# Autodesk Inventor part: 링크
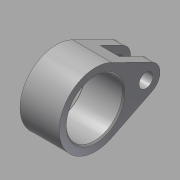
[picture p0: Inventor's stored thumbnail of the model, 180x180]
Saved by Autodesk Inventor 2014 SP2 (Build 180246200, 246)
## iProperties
Created: 2016-02
Part Number: 링크
Material: 강철, 연강
Document SubType Name: Modeling
Designer: test
Density: 1 g/cm^3
Appearance: 강철
Author: test
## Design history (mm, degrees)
sketch "스케치1"
  geometry: L1 (20.222, 4.479)-(5.778, 11.645); L2 (20.222, -4.479)-(5.778, -11.645); A1 r 13 centre (0, 0) between (5.778, 11.645) and (5.778, -11.645); A2 r 5 centre (18, 0) between (20.222, -4.479) and (20.222, 4.479); 1 further point
  constraints: 4 end point, 4 point on circle, 4 tangent, 2 centre point, 1 coincident, 1 horizontal alignment
  dimensions: "d0" = 18 distance of point (0, 0) A2.centre; "d1" = 13 radius of A1; "d2" = 5 radius of A2
extrude "돌출1" new body sketch "스케치1" stored distance "d3" = 14; taper "d4" = 0 deg
sketch "스케치2"
  geometry: C1 r 10 at (0, 0); 1 further point
  constraints: 1 centre point, 1 coincident
  dimensions: "d5" = 20 diameter of C1
extrude "돌출2" cut sketch "스케치2" stored distance "d6" = 14; taper "d7" = 0 deg
sketch "스케치3"
  geometry: C1 r 2.5 at (18, 0); A1 r 5 centre (18, 0) between (20.222, -4.479) and (20.222, 4.479) reference; 1 further point
  constraints: 1 centre point, 1 coincident
  dimensions: "d8" = 5 diameter of C1
extrude "돌출3" cut sketch "스케치3" stored distance "d9" = 14; taper "d10" = 0 deg
sketch "스케치4"
  geometry: L1 (20.222, -4.479)-(5.778, -11.645) reference; L2 (5.778, 11.645)-(20.222, 4.479) reference; L3 (12, 8.558)-(12, -8.558); C1 r 2.5 at (18, 0) reference; C2 r 10 at (0, 0) reference; A1 r 13 centre (0, 0) between (5.778, 11.645) and (5.778, -11.645) reference; A2 r 5 centre (18, 0) between (20.222, -4.479) and (20.222, 4.479) reference; 1 further point
  constraints: 2 end point, 2 point on line, 1 vertical
  dimensions: "d11" = 12 distance from line of L3 point (0, 0)
extrude "돌출4" cut sketch "스케치4" stored distance "d12" = 7; taper "d13" = 0 deg
chamfer "모따기1" distance "d14" = 0.5; stored, may be unused: second distance "d15" = 2, angle "d16" = 45 deg
node "솔리드1"
node "절단 모서리 투영1"
